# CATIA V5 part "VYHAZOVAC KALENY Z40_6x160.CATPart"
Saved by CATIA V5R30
Part number: VYHAZOVAC KALENY Z40/6x160
Bounding box of the stored display mesh (mm): x 0 to 153, y -6 to 6, z -6 to 6
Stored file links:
  C:\Users\ondra\Desktop\PŘÍLOHA P III\CATIA\VYHAZOVAC KALENY Z40_6x160.CATPart
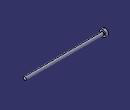
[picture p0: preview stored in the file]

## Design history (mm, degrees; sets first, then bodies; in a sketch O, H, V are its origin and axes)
Set1
  DatumSurface1 to DatumSurface9 "Z40/6x16"
  Join1: Elements (DatumSurface1; DatumSurface2; DatumSurface3; DatumSurface4; DatumSurface5; DatumSurface6; DatumSurface7; DatumSurface8; DatumSurface9)
Body1 (main body)
  CloseSurface1: CloseElement Join1
  Plane1: type Offset, RefPlane yz-plane, Offset 160
  DatumSurface10
  Sketch1 on Plane1, origin (160, 0, 0), H (0, 1, 0), V (0, 0, 1)
    projected circle E1 centre (0, 0) radius 3 from face of CloseSurface1
  Pocket1: profile Sketch1, direction (-1, 0, 0), up to face of DatumSurface10
  Plane2: type Offset, RefPlane yz-plane, Offset 146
